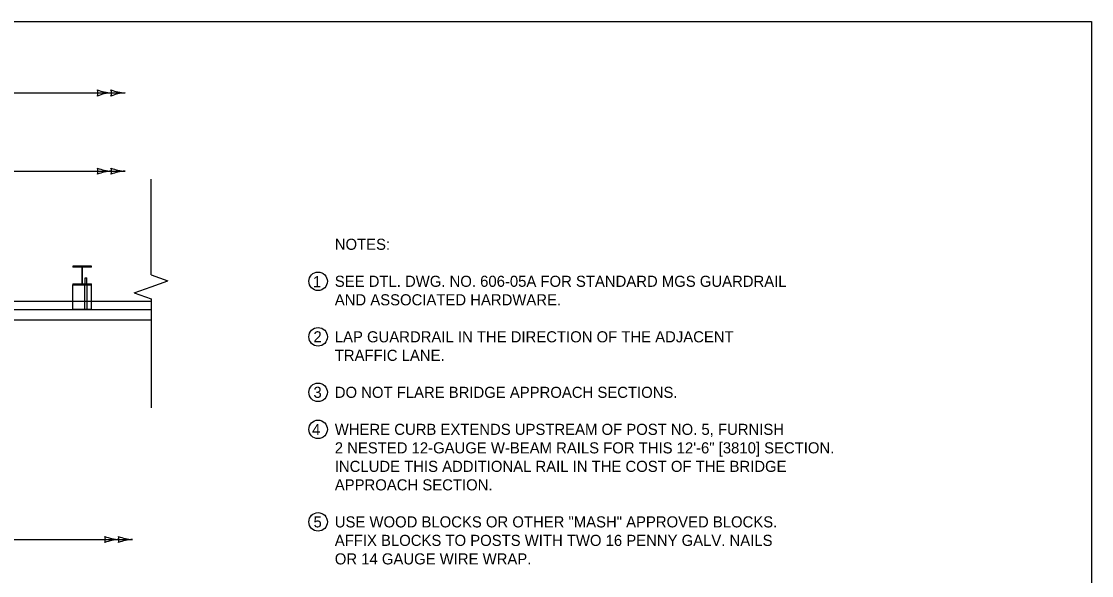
# Model space of a CAD drawing. Extents: x 49991 to 50160, y 49948 to 50051.
# Drawn here: x 50010.97 to 50016.75, y 49996 to 49999 of the extents above; entities that cross this region are included whole.
import ezdxf

# ---------------------------------------------------------------- set-up
doc = ezdxf.new("R2010")
doc.units = 0
for name, color, linetype in [('Level 1', 7, 'Continuous'), ('Level 2', 7, 'Continuous'), ('Level 3', 7, 'Continuous'), ('Level 4', 7, 'Continuous'), ('Level 6', 7, 'Continuous')]:
    doc.layers.add(name, color=color, linetype=linetype)

msp = doc.modelspace()

# ---------------------------------------------------------------- linework, layer by layer
at = {"layer": 'Level 1'}
for p, q in [((50011.3508, 49997.6763), (50011.2508, 49997.6763)), ((50011.2508, 49997.6763), (50011.2508, 49997.672)), ((50011.3508, 49997.672), (50011.2508, 49997.672)), ((50011.2989, 49997.672), (50011.2989, 49997.5806)), ((50011.3027, 49997.5806), (50011.3027, 49997.672)), ((50011.3508, 49997.672), (50011.3508, 49997.6763)), ((50011.2508, 49997.5806), (50011.2508, 49997.5763)), ((50011.2508, 49997.5806), (50011.3508, 49997.5806)), ((50011.2508, 49997.5763), (50011.3508, 49997.5763)), ((50011.2508, 49997.443), (50011.2508, 49997.5763)), ((50011.3508, 49997.5763), (50011.2508, 49997.5763)), ((50011.3164, 49997.614), (50011.3269, 49997.614)), ((50011.3164, 49997.5806), (50011.3164, 49997.614)), ((50011.3269, 49997.5806), (50011.3269, 49997.614)), ((50011.3508, 49997.5763), (50011.3508, 49997.5806)), ((50011.3508, 49997.443), (50011.3508, 49997.5763)), ((50010.1008, 49997.4868), (50011.2508, 49997.4868)), ((50011.3508, 49997.4868), (50011.6716, 49997.4868)), ((49999.8238, 49997.4433), (50011.6716, 49997.4428)), ((50011.3508, 49997.443), (50011.2508, 49997.443)), ((49999.8238, 49997.387), (50011.6716, 49997.3866))]:
    msp.add_line(p, q, dxfattribs=at)
msp.add_lwpolyline([(49999.3835, 49998.9992), (50016.7501, 49998.9992), (50016.7501, 49987.7988), (49999.3835, 49987.7988)], close=True, dxfattribs=at)
at = {"layer": 'Level 2'}
for centre in [(50012.5746, 49997.5948), (50012.5746, 49997.2948), (50012.5746, 49996.9948), (50012.5746, 49996.7948), (50012.5746, 49996.2948)]:
    msp.add_circle(centre, 0.05, dxfattribs=at)
at = {"layer": 'Level 3'}
for p, q in [((50008.1966, 49998.6127), (50011.5324, 49998.6127)), ((50006.3216, 49998.1899), (50011.5324, 49998.1899)), ((50010.0716, 49997.3868), (50011.3216, 49997.3868)), ((50008.1966, 49996.1994), (50011.5729, 49996.1994))]:
    msp.add_line(p, q, dxfattribs=at)
for centre, radius, start, end in [((50011.4681, 49998.8348), 0.2223, 247.45601, 267.63952), ((50011.3308, 49998.6127), 0.0548, 342.13882, 17.86118), ((50011.5416, 49998.8348), 0.2223, 247.45601, 267.63952), ((50011.4042, 49998.6127), 0.0548, 342.13882, 17.86118), ((50011.4705, 49998.38), 0.233, 92.82731, 112.07716), ((50011.5439, 49998.38), 0.233, 92.82731, 112.07716), ((50011.4681, 49998.412), 0.2223, 247.45601, 267.63952), ((50011.3308, 49998.1899), 0.0548, 342.13882, 17.86118), ((50011.4705, 49997.9572), 0.233, 92.82731, 112.07716), ((50011.5416, 49998.412), 0.2223, 247.45601, 267.63952), ((50011.4042, 49998.1899), 0.0548, 342.13882, 17.86118), ((50011.5439, 49997.9572), 0.233, 92.82731, 112.07716), ((50011.5086, 49996.4216), 0.2223, 247.45601, 267.63952), ((50011.3712, 49996.1994), 0.0548, 342.13882, 17.86118), ((50011.5109, 49995.9667), 0.233, 92.82731, 112.07716), ((50011.582, 49996.4216), 0.2223, 247.45601, 267.63952), ((50011.4447, 49996.1994), 0.0548, 342.13882, 17.86118), ((50011.5844, 49995.9667), 0.233, 92.82731, 112.07716)]:
    msp.add_arc(centre, radius, start, end, dxfattribs=at)
at = {"layer": 'Level 4'}
for p, q in [((50011.3154, 49997.443), (50011.3154, 49997.5763)), ((50011.3154, 49997.443), (50011.3154, 49997.5763)), ((50011.3279, 49997.443), (50011.3279, 49997.5763)), ((50011.3279, 49997.443), (50011.3279, 49997.5763)), ((50011.2508, 49997.4868), (50011.3508, 49997.4868))]:
    msp.add_line(p, q, dxfattribs=at)
at = {"layer": 'Level 6'}
for p, q in [((50011.6725, 49997.6298), (50011.6725, 49998.1459)), ((50011.6725, 49997.6298), (50011.7639, 49997.5974)), ((50011.6725, 49997.565), (50011.7639, 49997.5974)), ((50011.5811, 49997.5326), (50011.6725, 49997.565)), ((50011.5811, 49997.5326), (50011.6725, 49997.5002)), ((50011.6725, 49997.5002), (50011.6725, 49996.9118))]:
    msp.add_line(p, q, dxfattribs=at)

# ---------------------------------------------------------------- texts
at = {"layer": 'Level 2'}
for s, p in [('NOTES:', (50012.6646, 49997.7648)), ('1', (50012.5463, 49997.5628)), ('SEE DTL. DWG. NO. 606-05A FOR STANDARD MGS GUARDRAIL', (50012.6646, 49997.5648)), ('AND ASSOCIATED HARDWARE.', (50012.6646, 49997.4648)), ('2', (50012.5494, 49997.2648)), ('LAP GUARDRAIL IN THE DIRECTION OF THE ADJACENT', (50012.6646, 49997.2648)), ('TRAFFIC LANE.', (50012.6646, 49997.1648)), ('3', (50012.5494, 49996.9648)), ('DO NOT FLARE BRIDGE APPROACH SECTIONS.', (50012.6646, 49996.9648)), ('4', (50012.5419, 49996.7636)), ('WHERE CURB EXTENDS UPSTREAM OF POST NO. 5, FURNISH', (50012.6646, 49996.7648)), ('2 NESTED 12-GAUGE W-BEAM RAILS FOR THIS 12\'-6" [3810] SECTION.', (50012.6646, 49996.6648)), ('INCLUDE THIS ADDITIONAL RAIL IN THE COST OF THE BRIDGE', (50012.6646, 49996.5648)), ('APPROACH SECTION.', (50012.6646, 49996.4648)), ('5', (50012.5497, 49996.2648)), ('USE WOOD BLOCKS OR OTHER "MASH" APPROVED BLOCKS. ', (50012.6646, 49996.2648)), ('AFFIX BLOCKS TO POSTS WITH TWO 16 PENNY GALV. NAILS', (50012.6646, 49996.1648)), ('OR 14 GAUGE WIRE WRAP.', (50012.6646, 49996.0648))]:
    msp.add_text(s, height=0.06, dxfattribs=at).set_placement(p)

doc.saveas('drawing.dxf')
